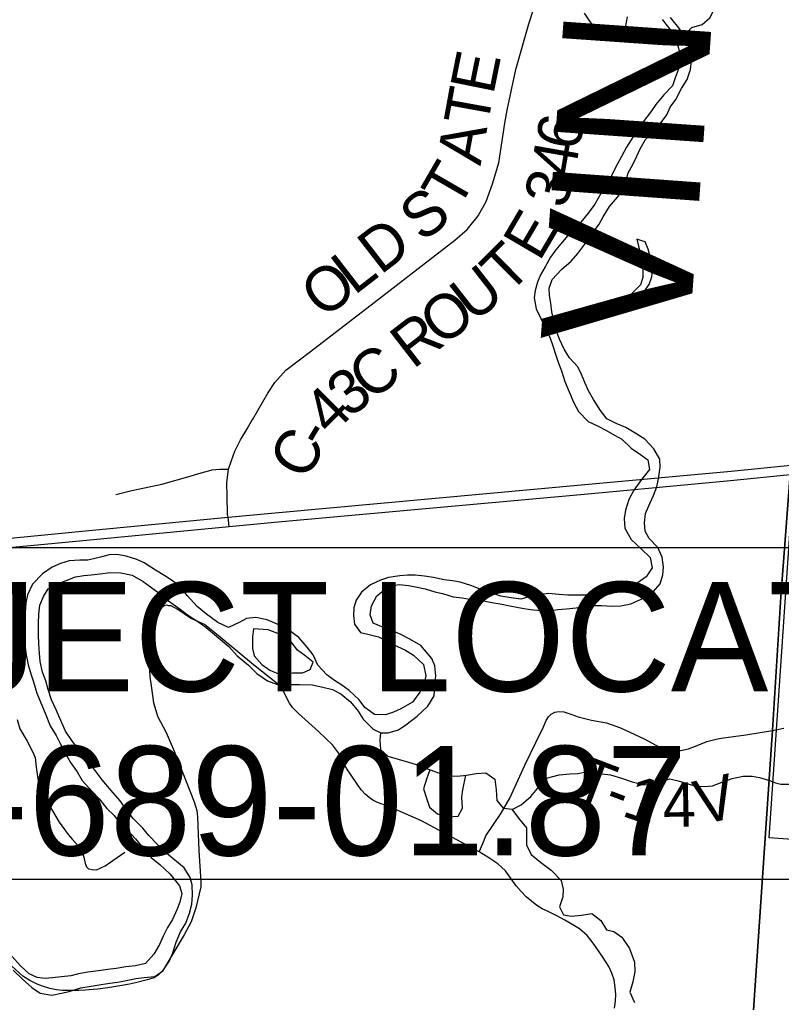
# Model space of a CAD drawing. Extents: x -13.7 to 34, y 0 to 32.3.
# Drawn here: x 24.865 to 25.84, y 17.876 to 19.134 of the extents above; entities that cross this region are included whole.
import ezdxf

# ---------------------------------------------------------------- set-up
doc = ezdxf.new("R2010")
doc.units = 0
for name, color, linetype in [('GM_X_Corporation', 7, 'Continuous'), ('GM_X_County_Road', 7, 'Continuous'), ('GM_X_County_Road_Text', 7, 'Continuous'), ('GM_X_County_Text', 7, 'Continuous'), ('GM_X_Major_River', 7, 'Continuous'), ('GM_X_Minor_Lake', 7, 'Continuous'), ('GM_X_Minor_River', 7, 'Continuous'), ('GM_X_State_Route', 7, 'Continuous'), ('GM_X_Township_Road', 7, 'Continuous'), ('GM_X_Township_Road_Text', 7, 'Continuous'), ('SH_Masking', 7, 'Continuous'), ('SH_Text', 7, 'Continuous')]:
    doc.layers.add(name, color=color, linetype=linetype)

msp = doc.modelspace()

# ---------------------------------------------------------------- linework, layer by layer
at = {"layer": 'GM_X_Corporation'}
for points in [[(29.9598, 20.9), (26.0026, 20.9), (25.9834, 20.5724), (25.9566, 20.1753), (25.9462, 20.0191), (25.9325, 19.8164), (25.917, 19.5276), (25.8969, 19.2407), (25.8969, 19.1723), (25.8715, 18.8281), (25.8521, 18.5644), (25.8512, 18.5523), (25.8396, 18.3951), (25.8286, 18.2247), (25.8036, 17.8534), (25.7648, 17.1991), (25.7595, 17.1252), (25.7591, 17.1039), (25.7561, 17.0683), (25.752, 17.037), (25.7481, 16.9763), (25.7164, 16.6052), (25.6857, 16.1459), (25.6733, 15.948)], [(29.9598, 20.9), (26.0026, 20.9), (25.9834, 20.5724), (25.9566, 20.1753), (25.9462, 20.0191), (25.9325, 19.8164), (25.917, 19.5276), (25.8969, 19.2407), (25.8969, 19.1723), (25.8715, 18.8281), (25.8521, 18.5644), (25.8512, 18.5523), (25.8396, 18.3951), (25.8286, 18.2247), (25.8036, 17.8534), (25.7648, 17.1991), (25.7595, 17.1252), (25.7591, 17.1039), (25.7561, 17.0683), (25.752, 17.037), (25.7481, 16.9763), (25.7164, 16.6052), (25.6857, 16.1459), (25.6733, 15.948)], [(25.6733, 15.948), (25.6857, 16.1459), (25.7164, 16.6052), (25.7481, 16.9763), (25.752, 17.037), (25.7561, 17.0683), (25.7591, 17.1039), (25.7595, 17.1252), (25.7648, 17.1991), (25.8036, 17.8534), (25.8286, 18.2247), (25.8396, 18.3951), (25.8512, 18.5523)], [(25.6733, 15.948), (25.6857, 16.1459), (25.7164, 16.6052), (25.7481, 16.9763), (25.752, 17.037), (25.7561, 17.0683), (25.7591, 17.1039), (25.7595, 17.1252), (25.7648, 17.1991), (25.8036, 17.8534), (25.8286, 18.2247), (25.8396, 18.3951), (25.8512, 18.5523)]]:
    msp.add_lwpolyline(points, dxfattribs=at)
msp.add_lwpolyline([(25.8944, 19.1175), (26.9188, 19.0522), (26.8924, 18.6876), (26.8578, 18.216), (26.8422, 18.014), (25.8244, 18.0867)], close=True, dxfattribs=at)
at = {"layer": 'GM_X_County_Road'}
for points in [[(25.1627, 18.6209), (25.1637, 18.6226), (25.183, 18.6561), (25.1921, 18.6696), (25.2061, 18.6855), (25.2375, 18.7094), (25.3193, 18.7723), (25.4224, 18.8519), (25.4383, 18.8655), (25.4522, 18.883), (25.4625, 18.9015), (25.4707, 18.9243), (25.4785, 18.9511), (25.4865, 19.0018), (25.4893, 19.0184), (25.5005, 19.0705), (25.5171, 19.1291), (25.5287, 19.1649), (25.5385, 19.1931), (25.5451, 19.2081), (25.5601, 19.2293)], [(25.1336, 18.4855), (25.1321, 18.4972), (25.1316, 18.5008), (25.1311, 18.524), (25.1306, 18.5412), (25.1325, 18.5588), (25.1366, 18.5697), (25.141, 18.5817), (25.1479, 18.5964), (25.1566, 18.6105), (25.1627, 18.6209)]]:
    msp.add_lwpolyline(points, dxfattribs=at)
at = {"layer": 'GM_X_Major_River'}
for points in [[(25.588, 19.1425), (25.5945, 19.1326), (25.6047, 19.1189), (25.6176, 19.1094), (25.6313, 19.1121), (25.6408, 19.1242), (25.6431, 19.1379)], [(25.6875, 19.1344), (25.6989, 19.1207), (25.7053, 19.1109), (25.7087, 19.098), (25.711, 19.0843), (25.7095, 19.0737), (25.7041, 19.06), (25.7007, 19.0498), (25.6897, 19.038), (25.6794, 19.0259), (25.6733, 19.0164), (25.6631, 19.0035), (25.6543, 18.991), (25.6478, 18.9804), (25.6418, 18.9709), (25.6357, 18.9591), (25.63, 18.9489), (25.6224, 18.9341), (25.6167, 18.9246), (25.609, 18.9117), (25.6014, 18.8981), (25.5931, 18.8867), (25.5836, 18.8749), (25.5691, 18.8605), (25.56, 18.8499), (25.5516, 18.8397), (25.5448, 18.8302), (25.5379, 18.8177), (25.5319, 18.8078), (25.528, 18.7983), (25.525, 18.7877), (25.5239, 18.7782), (25.5265, 18.7642), (25.5322, 18.7517), (25.5386, 18.738), (25.5443, 18.7266), (25.5477, 18.7167), (25.5515, 18.7046), (25.5549, 18.6947), (25.5587, 18.6845), (25.5632, 18.6712), (25.5685, 18.6579), (25.5746, 18.6439), (25.5807, 18.6325), (25.5928, 18.6199), (25.6057, 18.6139), (25.6156, 18.6089), (25.6266, 18.6025), (25.6361, 18.5971), (25.6478, 18.5858), (25.66, 18.5774), (25.6694, 18.5706), (25.6713, 18.5584), (25.6611, 18.5455), (25.6512, 18.5319), (25.6451, 18.5201), (25.6405, 18.5061), (25.639, 18.4954), (25.6397, 18.4833), (25.6481, 18.4685), (25.6606, 18.4567), (25.6724, 18.4457), (25.675, 18.4324), (25.667, 18.421), (25.6568, 18.4135), (25.6454, 18.4078), (25.6332, 18.4029), (25.6207, 18.3987), (25.6104, 18.3983), (25.6005, 18.3979), (25.5903, 18.3976), (25.5671, 18.3976), (25.5554, 18.3984), (25.5428, 18.3995), (25.5292, 18.398), (25.5189, 18.3957), (25.5067, 18.3923), (25.4942, 18.3938), (25.4813, 18.3961), (25.468, 18.4003), (25.4547, 18.4049), (25.4426, 18.4098)], [(25.4695, 18.3882), (25.4805, 18.3863), (25.4927, 18.3836), (25.5083, 18.3806), (25.5193, 18.379), (25.5322, 18.3779), (25.5432, 18.3775), (25.5542, 18.379), (25.5652, 18.3798), (25.5777, 18.3813), (25.5876, 18.3832), (25.6005, 18.3843), (25.61, 18.3843), (25.6229, 18.3835), (25.6347, 18.3839), (25.6476, 18.3861), (25.6609, 18.3922), (25.6734, 18.3987), (25.6852, 18.4119), (25.6883, 18.4233), (25.6894, 18.4332), (25.6875, 18.4461), (25.6819, 18.4586), (25.6709, 18.47), (25.6659, 18.4795), (25.6652, 18.4901), (25.6663, 18.5019), (25.6717, 18.5148), (25.6766, 18.525), (25.6808, 18.536), (25.6831, 18.5463), (25.685, 18.5614), (25.6846, 18.5717), (25.6771, 18.5846), (25.6653, 18.5971), (25.652, 18.6059), (25.641, 18.6119), (25.6289, 18.6173), (25.6167, 18.6233), (25.6088, 18.634), (25.5997, 18.648), (25.5932, 18.659), (25.5887, 18.6697), (25.5845, 18.6799), (25.5796, 18.6898), (25.569, 18.7015), (25.5621, 18.7126), (25.5561, 18.7251), (25.5519, 18.7368), (25.5493, 18.7471), (25.5466, 18.7604), (25.5451, 18.7714), (25.5436, 18.7813), (25.5432, 18.7907), (25.547, 18.8017), (25.5588, 18.8143), (25.571, 18.8252), (25.5797, 18.8351), (25.59, 18.8484), (25.5972, 18.8594), (25.6071, 18.8723), (25.6121, 18.8818), (25.6204, 18.895), (25.6303, 18.9072), (25.6379, 18.9174), (25.6417, 18.9273), (25.644, 18.9383), (25.6497, 18.9481), (25.655, 18.9595), (25.6596, 18.969), (25.6665, 18.9808), (25.6756, 18.9902), (25.6851, 19.0012), (25.6934, 19.0126), (25.698, 19.0225), (25.7049, 19.0323), (25.7125, 19.0464), (25.7197, 19.0577), (25.7239, 19.0706), (25.725, 19.0816), (25.7239, 19.0953), (25.7175, 19.1112), (25.7091, 19.1238), (25.6981, 19.1371)], [(25.4426, 18.4098), (25.4293, 18.414), (25.4194, 18.4159), (25.4088, 18.4171), (25.3951, 18.4201), (25.3837, 18.4216), (25.3716, 18.4228), (25.3617, 18.4228), (25.3519, 18.422), (25.3374, 18.4202), (25.3272, 18.4167), (25.3146, 18.4107), (25.3028, 18.4012), (25.296, 18.391), (25.293, 18.3811), (25.2926, 18.3712), (25.2941, 18.3602), (25.3017, 18.3496), (25.3111, 18.3473), (25.3248, 18.3439), (25.3396, 18.3363), (25.3491, 18.3317), (25.359, 18.3268), (25.3696, 18.3207), (25.3821, 18.3085), (25.3851, 18.2941), (25.3832, 18.2843), (25.3775, 18.2733), (25.368, 18.2604), (25.3532, 18.252), (25.3437, 18.2475), (25.3338, 18.2441), (25.3194, 18.2445), (25.3073, 18.2536), (25.2997, 18.2634), (25.2872, 18.2752), (25.2777, 18.2821), (25.2682, 18.2881), (25.2587, 18.2954), (25.2469, 18.3079), (25.2409, 18.3208), (25.2333, 18.331), (25.2227, 18.3432), (25.2083, 18.3538), (25.1942, 18.3607), (25.1821, 18.3656), (25.1676, 18.369), (25.1559, 18.3675), (25.1464, 18.3626), (25.1327, 18.3558), (25.119, 18.3626), (25.1046, 18.3729), (25.0928, 18.3828), (25.08, 18.3968), (25.072, 18.4067), (25.0625, 18.4147), (25.0511, 18.4223), (25.0394, 18.4295), (25.0249, 18.4386), (25.0154, 18.4432), (25.0018, 18.4473), (24.99, 18.4493), (24.9798, 18.4489), (24.9691, 18.4459), (24.9528, 18.4421), (24.9425, 18.4421), (24.9289, 18.4413), (24.9179, 18.4379), (24.9072, 18.4334), (24.8947, 18.4247), (24.8821, 18.4114), (24.8757, 18.3977), (24.8734, 18.3875), (24.8726, 18.375), (24.8722, 18.3647), (24.8722, 18.334), (24.8737, 18.3211), (24.8763, 18.3082), (24.8797, 18.2968), (24.8831, 18.2862), (24.8873, 18.2721), (24.8926, 18.2596), (24.8979, 18.2463), (24.9047, 18.23), (24.9123, 18.2178), (24.9172, 18.2076), (24.9229, 18.1969), (24.9305, 18.1829), (24.9392, 18.1711), (24.9453, 18.1601), (24.9582, 18.1461), (24.9673, 18.1366), (24.9772, 18.1244), (24.9866, 18.1153), (24.9935, 18.1051), (25.0037, 18.0959), (25.0136, 18.0853), (25.0257, 18.0709), (25.0337, 18.0614), (25.045, 18.0523), (25.0576, 18.0405)], [(25.0856, 18.0018), (25.0868, 18.0131), (25.086, 18.0264), (25.0838, 18.0359), (25.0758, 18.0481), (25.0614, 18.0602), (25.0511, 18.0686), (25.0417, 18.0781), (25.0307, 18.0895), (25.0231, 18.099), (25.0109, 18.1115), (25.0015, 18.1236), (24.9939, 18.1339), (24.9825, 18.1472), (24.9711, 18.1609), (24.9597, 18.1764), (24.9525, 18.1863), (24.9423, 18.1981), (24.9332, 18.2098), (24.9241, 18.2231), (24.9195, 18.2338), (24.9123, 18.2505), (24.9063, 18.2634), (24.9021, 18.2767), (24.8991, 18.2877), (24.8949, 18.2987), (24.8919, 18.3123), (24.8908, 18.323), (24.89, 18.3351), (24.8897, 18.3465), (24.8897, 18.3617), (24.8901, 18.3731), (24.8912, 18.3848), (24.8958, 18.3958), (24.9019, 18.4053), (24.9137, 18.4121), (24.925, 18.4163), (24.9368, 18.4208), (24.9475, 18.4227), (24.957, 18.4235), (24.9683, 18.4246), (24.9809, 18.4265), (24.9949, 18.4261), (25.0094, 18.4231), (25.0234, 18.4151), (25.0329, 18.4079), (25.0439, 18.3999), (25.056, 18.39), (25.0708, 18.3794), (25.0803, 18.3721), (25.0947, 18.363), (25.1042, 18.3558), (25.1175, 18.3448), (25.133, 18.3315), (25.144, 18.3197), (25.1585, 18.3076), (25.1691, 18.2969), (25.1824, 18.2878), (25.1956, 18.2829), (25.2108, 18.2829), (25.2237, 18.2832), (25.2397, 18.2825), (25.2515, 18.2802), (25.2659, 18.2764), (25.2765, 18.2711), (25.289, 18.2608), (25.2985, 18.2487), (25.305, 18.2388), (25.3179, 18.2259), (25.3277, 18.2209), (25.3372, 18.2213), (25.3501, 18.2251), (25.3596, 18.2315), (25.3741, 18.2425), (25.3878, 18.2554), (25.3957, 18.2683), (25.3969, 18.2816), (25.398, 18.2941), (25.3969, 18.307), (25.3931, 18.3165), (25.3787, 18.3328), (25.3647, 18.3412), (25.3525, 18.3473), (25.3408, 18.3526), (25.3309, 18.356), (25.318, 18.3617), (25.3138, 18.372), (25.3157, 18.3837), (25.3226, 18.3966), (25.3386, 18.4095), (25.3515, 18.411), (25.3632, 18.4099), (25.3742, 18.4076), (25.3845, 18.4053), (25.3966, 18.4015), (25.4065, 18.3996), (25.4202, 18.3954), (25.4316, 18.3939), (25.4456, 18.3916), (25.457, 18.3905), (25.4695, 18.3882)], [(25.1645, 18.3543), (25.1634, 18.344), (25.1634, 18.3292), (25.1657, 18.3198), (25.1755, 18.3088), (25.1858, 18.3012), (25.1998, 18.2955), (25.2146, 18.2978), (25.2274, 18.2978), (25.2325, 18.3)], [(25.2325, 18.3), (25.2373, 18.302), (25.2411, 18.3115), (25.2304, 18.3202), (25.221, 18.327), (25.2111, 18.3399), (25.1978, 18.3475), (25.1834, 18.3528), (25.1645, 18.3543)], [(25.0576, 18.0405), (25.0701, 18.0253), (25.0731, 18.0154), (25.0704, 18.0041), (25.0666, 17.9946), (25.0609, 17.982), (25.0548, 17.9718), (25.0491, 17.9608), (25.0442, 17.9502), (25.0373, 17.9377), (25.0263, 17.9259), (25.0138, 17.9229), (25.0012, 17.9214), (24.9891, 17.9191), (24.9781, 17.918), (24.9663, 17.9165), (24.9526, 17.9146), (24.9409, 17.9123), (24.931, 17.91), (24.9188, 17.9085), (24.9074, 17.9074), (24.898, 17.9063), (24.8877, 17.9078), (24.8778, 17.9124), (24.8668, 17.9222), (24.8551, 17.9355)], [(24.857, 17.9173), (24.8691, 17.9055), (24.8812, 17.8949), (24.8919, 17.8877), (24.9067, 17.885), (24.9192, 17.8877), (24.9287, 17.8899), (24.9439, 17.8945), (24.9568, 17.8967), (24.9697, 17.899), (24.9807, 17.9005), (24.9906, 17.902), (25.0001, 17.9035), (25.0141, 17.9066), (25.0248, 17.9077), (25.0384, 17.9092), (25.0487, 17.9164), (25.0571, 17.9293), (25.0613, 17.9392), (25.0658, 17.9532), (25.0712, 17.9661), (25.078, 17.9775), (25.0826, 17.99), (25.0856, 18.0018)]]:
    msp.add_lwpolyline(points, dxfattribs=at)
at = {"layer": 'GM_X_Minor_Lake'}
for points in [[(25.6615, 18.8512), (25.6552, 18.8532), (25.6582, 18.8407), (25.6605, 18.8308), (25.6628, 18.8172), (25.6628, 18.8043), (25.6598, 18.7948), (25.6469, 18.7819), (25.6333, 18.7769), (25.6231, 18.7724), (25.6117, 18.7701), (25.5935, 18.761)], [(25.5935, 18.761), (25.6057, 18.7595), (25.6163, 18.7602), (25.6276, 18.7618), (25.6379, 18.7659), (25.65, 18.7732), (25.6613, 18.7815), (25.6708, 18.7952), (25.6742, 18.8051), (25.6757, 18.8179), (25.6722, 18.8305), (25.6696, 18.8403), (25.6658, 18.8498), (25.6615, 18.8512)]]:
    msp.add_lwpolyline(points, dxfattribs=at)
at = {"layer": 'GM_X_Minor_River'}
for points in [[(25.7155, 19.1142), (25.7257, 19.1244), (25.7386, 19.1282), (25.7488, 19.1369), (25.7548, 19.1483), (25.762, 19.1623), (25.7737, 19.1752), (25.7851, 19.1787), (25.8059, 19.1787), (25.8184, 19.1757), (25.8313, 19.1696), (25.8453, 19.1651), (25.8582, 19.1606), (25.87, 19.1583), (25.8921, 19.1463)], [(25.3272, 18.2212), (25.3264, 18.2115), (25.3272, 18.1998), (25.3367, 18.1911), (25.3632, 18.1835), (25.3727, 18.1805), (25.3825, 18.1767), (25.3954, 18.1718), (25.4049, 18.1688), (25.4159, 18.1661), (25.4253, 18.1654), (25.4371, 18.1669), (25.4496, 18.1692), (25.4621, 18.17), (25.4734, 18.1617), (25.475, 18.148), (25.4761, 18.1344), (25.4841, 18.1245), (25.4966, 18.1234), (25.5072, 18.1287), (25.5197, 18.1394), (25.528, 18.15), (25.5397, 18.1629), (25.556, 18.1675), (25.5693, 18.1686), (25.5791, 18.169), (25.5893, 18.1706), (25.6007, 18.1713), (25.6109, 18.1687), (25.6215, 18.1672), (25.6356, 18.163), (25.6492, 18.1585), (25.6625, 18.1551), (25.6731, 18.1547), (25.6856, 18.1589), (25.6973, 18.1624), (25.7083, 18.1597), (25.7178, 18.1567), (25.7306, 18.1526), (25.742, 18.1522), (25.7519, 18.1533), (25.7666, 18.1587), (25.7772, 18.1625), (25.7912, 18.1655), (25.8026, 18.1655), (25.8121, 18.1637), (25.825, 18.1599)], [(25.3905, 18.1737), (25.3859, 18.1619), (25.3822, 18.1494), (25.3867, 18.1361), (25.3898, 18.1259), (25.4, 18.1172), (25.4133, 18.1134), (25.4265, 18.1142), (25.4322, 18.1248), (25.4314, 18.1389), (25.4325, 18.1483), (25.4365, 18.1669)], [(25.4953, 18.1235), (25.5038, 18.1117), (25.514, 18.0995), (25.5141, 18.0776), (25.5198, 18.0654), (25.5319, 18.0556), (25.5456, 18.0454), (25.5584, 18.0321), (25.5611, 18.0207), (25.5604, 18.0109), (25.5562, 17.9984), (25.5615, 17.9881), (25.5714, 17.9862), (25.5846, 17.9878), (25.5975, 17.9897), (25.6093, 17.9806), (25.6165, 17.9689), (25.6259, 17.9666), (25.6358, 17.9594), (25.6457, 17.945), (25.6521, 17.9276), (25.6525, 17.9151), (25.6503, 17.9022), (25.6461, 17.8889), (25.6522, 17.8756)]]:
    msp.add_lwpolyline(points, dxfattribs=at)
msp.add_spline([(25.825, 18.1599), (25.8292, 18.1584), (25.8429, 18.1552), (25.8456, 18.1555), (25.8516, 18.1553), (25.8577, 18.1551), (25.8603, 18.1546), (25.8778, 18.1541), (25.8808, 18.1543), (25.8831, 18.1547), (25.8858, 18.1553), (25.8885, 18.1564), (25.8904, 18.1567), (25.8942, 18.1581), (25.8993, 18.1606), (25.9062, 18.1641), (25.9116, 18.167), (25.9139, 18.1677), (25.9178, 18.1695), (25.922, 18.1716), (25.9289, 18.1744), (25.9351, 18.1776), (25.9386, 18.1787), (25.9451, 18.1807), (25.9478, 18.181), (25.9535, 18.1823), (25.9569, 18.1826), (25.9596, 18.1833), (25.9665, 18.1838), (25.9703, 18.1844), (25.9729, 18.1844), (25.9779, 18.1846), (25.9805, 18.1845), (25.9851, 18.1839), (25.987, 18.1839), (25.9911, 18.183), (25.9938, 18.1829), (25.9975, 18.182), (25.9994, 18.182), (26.0028, 18.1811), (26.0043, 18.1807), (26.0069, 18.1802), (26.0103, 18.1793), (26.0118, 18.1789), (26.0134, 18.1788), (26.0152, 18.1784), (26.0167, 18.178), (26.0194, 18.1775), (26.0209, 18.1774), (26.0224, 18.177), (26.0243, 18.1769), (26.0262, 18.1765), (26.0285, 18.1764), (26.0304, 18.1767), (26.0323, 18.1771), (26.0357, 18.1773), (26.0372, 18.178), (26.0388, 18.1784), (26.0407, 18.1791), (26.0426, 18.1794), (26.0445, 18.1805), (26.0461, 18.1812), (26.0495, 18.1826), (26.0511, 18.1829), (26.0541, 18.1839), (26.0557, 18.1843), (26.0591, 18.1853), (26.0607, 18.1856), (26.0633, 18.1859), (26.0648, 18.1862), (26.0671, 18.1866), (26.0687, 18.1869), (26.0713, 18.1872), (26.0763, 18.187), (26.0782, 18.1873), (26.093, 18.1868), (26.0952, 18.1864), (26.0971, 18.1863), (26.0994, 18.1859), (26.102, 18.1854), (26.1054, 18.1845), (26.1221, 18.184), (26.1251, 18.1842), (26.1346, 18.1839), (26.1471, 18.1835), (26.1494, 18.1838), (26.1672, 18.1832), (26.1703, 18.1835), (26.1737, 18.1838), (26.1775, 18.184), (26.1832, 18.1846), (26.1859, 18.1849), (26.192, 18.1851), (26.1965, 18.1853)], degree=3, dxfattribs=at)
at = {"layer": 'GM_X_State_Route'}
for points in [[(24.8051, 18.4658), (24.9497, 18.4797), (25.1321, 18.4972), (25.1923, 18.5029), (25.5934, 18.5394), (25.7758, 18.5564), (25.8523, 18.5638)], [(24.8067, 18.4541), (24.9512, 18.4679), (25.1336, 18.4855), (25.1914, 18.4908), (25.5925, 18.5273), (25.7749, 18.5443), (25.8514, 18.5518)]]:
    msp.add_lwpolyline(points, dxfattribs=at)
at = {"layer": 'GM_X_Township_Road'}
for points in [[(24.9887, 18.5262), (25.0089, 18.5314), (25.0173, 18.5332), (25.0473, 18.5395), (25.0836, 18.5498), (25.0936, 18.5526), (25.1009, 18.5549), (25.1105, 18.5575)], [(25.1105, 18.5575), (25.1113, 18.5577), (25.1216, 18.5587), (25.1325, 18.5588)], [(25.6265, 17.8684), (25.6281, 17.8774), (25.6284, 17.8858), (25.6273, 17.8948), (25.6261, 17.9047), (25.6233, 17.9134), (25.6194, 17.9218), (25.6119, 17.9336), (25.5994, 17.9517), (25.5918, 17.9616), (25.5817, 17.97), (25.5732, 17.9754), (25.5629, 17.9813), (25.5527, 17.9868), (25.5427, 17.9917), (25.5341, 17.9955), (25.5274, 17.9999), (25.5135, 18.0112), (25.5071, 18.0179), (25.5009, 18.0252), (25.4914, 18.0386), (25.4871, 18.0444), (25.4775, 18.0534), (25.4647, 18.0618), (25.4536, 18.0688), (25.4306, 18.0812), (25.3795, 18.1086), (25.3389, 18.1262), (25.3293, 18.1297), (25.3232, 18.132), (25.3175, 18.1347), (25.3127, 18.1381), (25.3076, 18.1425), (25.3026, 18.148), (25.2841, 18.175), (25.2733, 18.1956), (25.2658, 18.2059), (25.2477, 18.2227), (25.2222, 18.2458), (25.2148, 18.2535), (25.2109, 18.2592), (25.2012, 18.2775), (25.1954, 18.2839), (25.1649, 18.3083), (25.1219, 18.3438), (25.1022, 18.3598), (25.0915, 18.3644), (25.0842, 18.3681), (25.0679, 18.3792), (25.0595, 18.3836), (25.0563, 18.3838), (25.054, 18.3844), (25.0504, 18.3838), (25.0458, 18.3804), (25.042, 18.3757), (25.0398, 18.3702), (25.0369, 18.3638), (25.0345, 18.3577), (25.0314, 18.3492), (25.0307, 18.3432), (25.0299, 18.3351), (25.0299, 18.3244), (25.031, 18.3093), (25.0319, 18.293), (25.0339, 18.2811), (25.0368, 18.2595), (25.0383, 18.2538), (25.042, 18.2426), (25.0528, 18.2217), (25.0632, 18.1976), (25.074, 18.1707), (25.0889, 18.1329), (25.092, 18.1216), (25.0932, 18.1132), (25.0947, 18.0702), (25.0975, 18.0301), (25.0972, 18.0238), (25.0908, 17.9969), (25.085, 17.9792), (25.076, 17.9622), (25.0482, 17.9159), (25.0433, 17.9114), (25.0374, 17.9075), (25.0287, 17.9047), (25.0137, 17.9009), (25.006, 17.8991), (24.9938, 17.897), (24.9784, 17.8945), (24.9651, 17.893), (24.9495, 17.8916), (24.9413, 17.8913), (24.93, 17.8913), (24.9204, 17.8912), (24.9128, 17.8918), (24.9039, 17.8936), (24.8949, 17.8965), (24.8878, 17.8994), (24.8786, 17.904), (24.8695, 17.9093), (24.8556, 17.9223)], [(25.4536, 18.0688), (25.4581, 18.0795), (25.4622, 18.0891), (25.4815, 18.1183), (25.4928, 18.1376), (25.5121, 18.1798), (25.5258, 18.2087), (25.5356, 18.2289), (25.539, 18.2369), (25.5423, 18.2414), (25.5454, 18.2451), (25.5503, 18.2477), (25.5552, 18.2483), (25.5617, 18.2482), (25.5706, 18.2449), (25.58, 18.2414), (25.5973, 18.2375), (25.6166, 18.2339), (25.6341, 18.2274), (25.6648, 18.2133), (25.6795, 18.2055), (25.6896, 18.2001), (25.6977, 18.1978), (25.7072, 18.1975), (25.7213, 18.2004), (25.7303, 18.2041), (25.7447, 18.2098), (25.7567, 18.2129), (25.763, 18.2142), (25.7948, 18.2187), (25.8288, 18.2242)], [(24.8622, 18.2383), (24.8658, 18.2261), (24.875, 18.2105), (24.882, 18.1973), (24.8852, 18.1897), (24.8866, 18.1773), (24.8892, 18.1593), (24.894, 18.1441), (24.8988, 18.1357), (24.9162, 18.1067), (24.9274, 18.0909), (24.9328, 18.0849), (24.9406, 18.0761), (24.9448, 18.0703), (24.9476, 18.0619), (24.9494, 18.0536), (24.9508, 18.0494), (24.9534, 18.0468), (24.9582, 18.046), (24.9636, 18.0457), (24.9748, 18.0509), (25.0002, 18.0683)], [(25.8288, 18.2242), (25.8432, 18.2272)]]:
    msp.add_lwpolyline(points, dxfattribs=at)
at = {"layer": 'SH_Masking'}
msp.add_lwpolyline([(24.3829, 18.4583), (26.173, 18.4583), (26.173, 18.0332), (24.3829, 18.0332)], close=True, dxfattribs=at)
at = {"layer": 'SH_Text'}
msp.add_lwpolyline([(24.3829, 18.4583), (26.173, 18.4583), (26.173, 18.0332), (24.3829, 18.0332)], close=True, dxfattribs=at)

# ---------------------------------------------------------------- texts
at = {"layer": 'GM_X_County_Road_Text'}
for s, rotation, p in [('E', 78.532, (25.4715, 19.0372)), ('T', 79.702, (25.4639, 18.9957)), ('6', 79.576, (25.581, 18.9654)), ('A', 79.8433, (25.4551, 18.9465)), ('4', 80.1171, (25.575, 18.9311)), ('T', 59.9468, (25.4265, 18.8896)), ('3', 73.9149, (25.5638, 18.8909)), ('S', 38.0351, (25.3808, 18.8482)), ('E', 59.5716, (25.5305, 18.8235)), ('D', 37.7427, (25.3272, 18.8067)), ('T', 44.7663, (25.4905, 18.7809)), ('L', 37.7442, (25.2936, 18.7806)), ('O', 37.7501, (25.254, 18.75)), ('U', 37.9327, (25.4456, 18.7453)), ('O', 37.7167, (25.4058, 18.7145)), ('R', 37.6583, (25.3688, 18.686)), ('C', 37.5943, (25.3148, 18.6447)), ('3', 37.7317, (25.2871, 18.6233)), ('4', 45.1545, (25.2639, 18.5998)), ('-', 59.2558, (25.2543, 18.5827)), ('C', 60.8089, (25.2317, 18.5423))]:
    msp.add_text(s, height=0.0568, rotation=rotation, dxfattribs=at).set_placement(p)
at = {"layer": 'GM_X_County_Text'}
for s, rotation, p in [('N', 85.9918, (25.7389, 18.9568)), ('I', 85.8516, (25.7333, 18.879)), ('V', 85.8425, (25.7211, 18.7119))]:
    msp.add_text(s, height=0.1894, rotation=rotation, dxfattribs=at).set_placement(p)
at = {"layer": 'GM_X_Township_Road_Text'}
for s, rotation, p in [('T', 339.2062, (25.571, 18.1393)), ('1', 340.7776, (25.6342, 18.1154)), ('V', 12.9473, (25.7365, 18.1027)), ('4', 1.1403, (25.6889, 18.1005)), ('-', 339.3769, (25.6109, 18.1242))]:
    msp.add_text(s, height=0.0568, rotation=rotation, dxfattribs=at).set_placement(p)
at = {"layer": 'SH_Text'}
for s, p in [('PROJECT LOCATION', (24.388, 18.2741)), ('MEG-689-01.87', (24.388, 18.0641))]:
    msp.add_text(s, height=0.14, dxfattribs=at).set_placement(p)

doc.saveas('drawing.dxf')
